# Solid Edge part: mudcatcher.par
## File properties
Author: morva
Template: iso metric part.par
Last saved by: morva
Revision: 16
Application: Solid Edge
Density: 1385.000 kg/m^3
Accuracy: 0.990
Username: morva
Material: PVC
Face Style: Tan
Fill Style: ANSI34(Plastic)
Virtual Style: ANSI34(Plastic)
Grouping: Non-metals\Plastics
LibraryName: Materials
Coef. of Thermal Exp: 9e-05
Thermal Conductivity: 1.5
Specific Heat: 0.0
Modulus of Elasticity: 2757903000.0
Poisson's Ratio: 0.4
Yield Stress: 6894757.0
Ultimate Stress: 0.0
Elongation: 0.0
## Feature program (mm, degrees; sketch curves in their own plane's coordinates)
sketch for "unnamed RevolvedProtrusion 1" plane through (0, 0, 0) normal (0, 0, 1) x-axis (1, 0, 0)
  line (-41, 138.5472) -> (-41, 143.9844)
  line (41, 138.5472) -> (41, 143.9844)
revolve "unnamed RevolvedProtrusion 1" add finite
sketch for "ExtrudedCutout_1" plane through (0, 0, 0) normal (0, -0.707107, -0.707107) x-axis (-1, 0, 0)
  circle centre (0, 0) radius 4
extrude "ExtrudedCutout_1" cut finite 174.8905 along -normal
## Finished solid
Body 1: solid body, 7 faces, 14 edges, 8 vertices.
  Faces by surface: plane 4, torus 2, cylinder 1
  Edges by curve: circle 8, line 4, intersection 2
Bounding box of the edges (mm; curved faces can reach further): 82.000 x 285.940 x 143.984, from (-41, -118.4404, 0) to (41, 167.5, 143.9844).
Cylindrical faces by radius (mm): R4 x1
Toroidal faces (ring radius, tube radius in mm): R120 r45 x1, R120 r47.5 x1
Planar faces by outward normal: +x 1, -x 1, -z 1, oblique 1
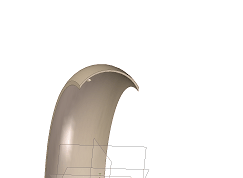
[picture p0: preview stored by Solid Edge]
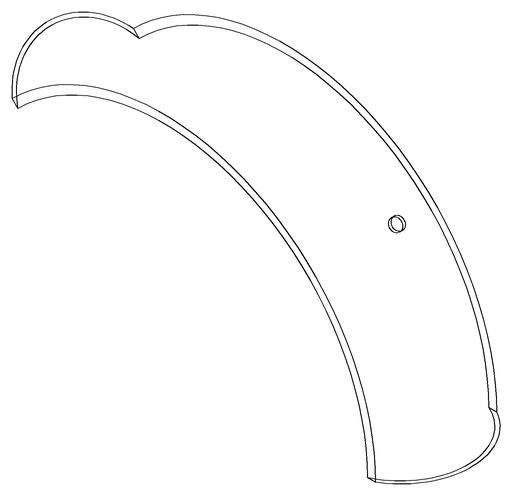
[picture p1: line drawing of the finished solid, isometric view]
